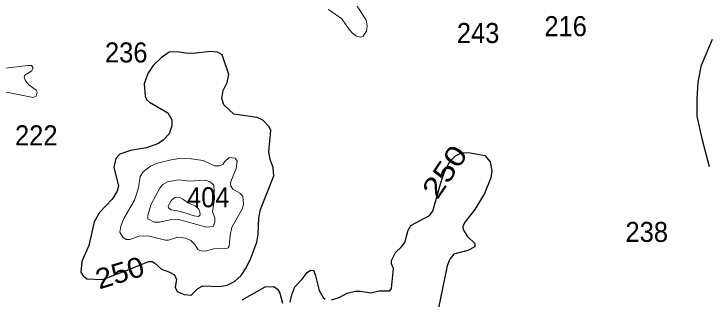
# Model space of a CAD drawing. Extents: x 499.9 to 555.3, y 9281.5 to 9336.8.
# Drawn here: x 526.97 to 532.51, y 9290.82 to 9293.1 of the extents above; entities that cross this region are included whole.
import ezdxf
from ezdxf.enums import TextEntityAlignment as Align

# ---------------------------------------------------------------- set-up
doc = ezdxf.new("R2010")
doc.units = 0
doc.header["$LTSCALE"] = 0.064
doc.layers.add('1', color=7, linetype='Continuous', lineweight=25)
doc.layers.add('2', color=7, linetype='Continuous', lineweight=13)
doc.layers.add('21', color=7, linetype='Continuous')
doc.layers.add('61', color=7, linetype='Continuous')

msp = doc.modelspace()

# ---------------------------------------------------------------- linework, layer by layer
at = {"layer": '1'}
for points in [[(532.5213, 9291.877), (532.4646, 9292.0881), (532.4233, 9292.2803), (532.4227, 9292.419), (532.4306, 9292.551), (532.4564, 9292.6863), (532.5451, 9292.8957)], [(530.0159, 9291.1934), (530.0639, 9291.2373), (530.092, 9291.2732), (530.1179, 9291.3716), (530.1405, 9291.4089), (530.288, 9291.4891), (530.3148, 9291.5231), (530.3747, 9291.7412), (530.4073, 9291.8356), (530.4498, 9291.9184), (530.4959, 9291.9634), (530.5497, 9291.9912), (530.6114, 9291.9884), (530.7298, 9291.9661), (530.7731, 9291.9174), (530.7848, 9291.8421), (530.777, 9291.7887), (530.728, 9291.6629), (530.6485, 9291.5355), (530.5686, 9291.4346), (530.5546, 9291.4018), (530.5579, 9291.3766), (530.5897, 9291.3234), (530.6502, 9291.2639), (530.6495, 9291.2397), (530.5947, 9291.21), (530.4827, 9291.1796), (530.4512, 9291.1391), (530.4291, 9291.0863), (530.3602, 9290.7522)], [(529.9719, 9290.8879), (529.9843, 9290.9053), (530.0016, 9291.0645), (529.9846, 9291.102), (529.986, 9291.1283), (530.0159, 9291.1934)], [(529.1775, 9290.7972), (529.1902, 9290.8552), (529.2147, 9290.9195), (529.2739, 9290.9804), (529.3128, 9291.0334), (529.3383, 9291.0523), (529.3662, 9291.0505), (529.3726, 9291.0302), (529.3785, 9291.0076), (529.4084, 9290.8903), (529.4396, 9290.8337), (529.4555, 9290.8203)], [(528.7957, 9290.8148), (528.9778, 9290.9185), (529.0479, 9290.9232), (529.077, 9290.8996), (529.0954, 9290.8678), (529.1156, 9290.7887)], [(529.5078, 9290.8166), (529.5673, 9290.8347), (529.6319, 9290.8697), (529.6947, 9290.8853), (529.7384, 9290.8854), (529.8212, 9290.8713), (529.8866, 9290.887), (529.9719, 9290.8879)]]:
    msp.add_lwpolyline(points, dxfattribs=at)
msp.add_lwpolyline([(527.6817, 9290.9779), (527.8441, 9291.0399), (528.0494, 9291.1223), (528.0769, 9291.1214), (528.0981, 9291.1086), (528.1507, 9291.0616), (528.2113, 9291.0394), (528.2556, 9291.0142), (528.2716, 9290.9787), (528.2597, 9290.9167), (528.2756, 9290.8825), (528.333, 9290.8583), (528.3887, 9290.8522), (528.44, 9290.907), (528.482, 9290.9282), (528.6166, 9290.9227), (528.6761, 9290.9318), (528.7342, 9290.9631), (528.7855, 9291.0098), (528.8225, 9291.0638), (528.8616, 9291.1403), (528.911, 9291.2766), (528.9235, 9291.3382), (528.9276, 9291.4688), (528.9405, 9291.5372), (529.0467, 9291.8039), (529.0421, 9291.8698), (529.017, 9291.9336), (529.0073, 9291.9972), (529.0227, 9292.1658), (529.0112, 9292.1959), (528.9602, 9292.2496), (528.9142, 9292.2693), (528.7279, 9292.2956), (528.6481, 9292.3699), (528.632, 9292.4202), (528.6441, 9292.4842), (528.6743, 9292.5488), (528.6885, 9292.6123), (528.6352, 9292.7684), (528.5981, 9292.7912), (528.536, 9292.7952), (528.4076, 9292.7811), (528.3418, 9292.7827), (528.2782, 9292.7936), (528.2122, 9292.7904), (528.1499, 9292.7465), (528.0847, 9292.6843), (528.0431, 9292.6216), (528.0142, 9292.5372), (528.0204, 9292.4412), (528.0327, 9292.4129), (528.0556, 9292.3916), (528.202, 9292.3076), (528.2332, 9292.2516), (528.2349, 9292.2042), (528.2138, 9292.1407), (528.1667, 9292.092), (528.1269, 9292.0634), (528.0307, 9292.0286), (527.9047, 9292.0063), (527.8199, 9291.9771), (527.7882, 9291.9422), (527.7724, 9291.873), (527.8084, 9291.7226), (527.7992, 9291.6836), (527.7576, 9291.6193), (527.6575, 9291.5125), (527.6134, 9291.4384), (527.572, 9291.2489), (527.5162, 9291.1202), (527.5085, 9291.036), (527.5283, 9291.0059), (527.5558, 9290.9829)], close=True, dxfattribs=at)
at = {"layer": '2'}
for points in [[(529.4832, 9293.1312), (529.5895, 9293.0562), (529.6465, 9292.9727), (529.6772, 9292.9387), (529.706, 9292.9182), (529.7377, 9292.9113), (529.7587, 9292.9187), (529.7864, 9292.959), (529.79, 9293.0007), (529.7836, 9293.0451), (529.7047, 9293.1719)], [(526.6326, 9292.5279), (527.1289, 9292.4298), (527.1529, 9292.4394), (527.1607, 9292.4722), (527.1528, 9292.488), (527.0949, 9292.5309), (527.0673, 9292.5615), (527.0565, 9292.5916), (527.0622, 9292.6083), (527.1185, 9292.6431), (527.1259, 9292.6581), (527.1258, 9292.6697), (527.1179, 9292.6827), (527.1139, 9292.6847), (527.086, 9292.6853), (526.9088, 9292.6642)]]:
    msp.add_lwpolyline(points, dxfattribs=at)
for points in [[(528.7967, 9291.5436), (528.804, 9291.5788), (528.8001, 9291.6413), (528.7754, 9291.6665), (528.7206, 9291.6993), (528.7025, 9291.727), (528.7044, 9291.7607), (528.7458, 9291.8637), (528.7536, 9291.9204), (528.7393, 9291.9467), (528.6909, 9291.9503), (528.6541, 9291.9172), (528.6406, 9291.8962), (528.6109, 9291.8835), (528.5742, 9291.8851), (528.4843, 9291.9264), (528.3881, 9291.9405), (528.2917, 9291.9423), (528.229, 9291.9334), (528.1207, 9291.9046), (528.0648, 9291.8824), (528.0052, 9291.8359), (527.9818, 9291.8006), (527.9691, 9291.7099), (527.9375, 9291.61), (527.8514, 9291.4653), (527.826, 9291.402), (527.8199, 9291.3547), (527.8433, 9291.3165), (527.8692, 9291.2977), (527.9001, 9291.2964), (527.9712, 9291.3227), (528.0433, 9291.3261), (528.1827, 9291.2914), (528.2086, 9291.2917), (528.2822, 9291.3152), (528.3465, 9291.3084), (528.3848, 9291.2896), (528.4152, 9291.2604), (528.4437, 9291.2155), (528.466, 9291.2055), (528.5017, 9291.2042), (528.5664, 9291.2231), (528.6696, 9291.2247), (528.6823, 9291.2295), (528.6919, 9291.2442), (528.6986, 9291.3312), (528.7118, 9291.3948)], [(528.577, 9291.4692), (528.5582, 9291.5173), (528.5745, 9291.6226), (528.5683, 9291.73), (528.5391, 9291.7558), (528.497, 9291.7688), (528.3737, 9291.7625), (528.2902, 9291.7735), (528.1989, 9291.7574), (528.1631, 9291.7348), (528.1394, 9291.706), (528.0685, 9291.5785), (528.0427, 9291.4912), (528.0437, 9291.4624), (528.0937, 9291.4348), (528.1357, 9291.4348), (528.2178, 9291.4537), (528.2784, 9291.46), (528.5092, 9291.3949), (528.5642, 9291.4016), (528.5755, 9291.436)], [(528.3021, 9291.5215), (528.4114, 9291.4846), (528.4475, 9291.4814), (528.4598, 9291.4934), (528.4571, 9291.5174), (528.4491, 9291.5388), (528.421, 9291.5656), (528.3676, 9291.587), (528.3222, 9291.6174), (528.2932, 9291.6343), (528.2591, 9291.6316), (528.2302, 9291.6105), (528.2056, 9291.5617), (528.2074, 9291.5503), (528.2281, 9291.5334)]]:
    msp.add_lwpolyline(points, close=True, dxfattribs=at)

# ---------------------------------------------------------------- texts
at = {"layer": '21', "width": 0.95}
for s, p in [('216', (531.2039, 9292.9184)), ('243', (530.5061, 9292.8636)), ('236', (527.7008, 9292.7088)), ('222', (526.9836, 9292.0476)), ('404', (528.3552, 9291.5539)), ('238', (531.8507, 9291.2776))]:
    msp.add_text(s, height=0.16, dxfattribs=at).set_placement(p)
at = {"layer": '61'}
for rotation, width, p in [(55.84, 1.25, (530.4752, 9291.7932)), (17.162, 1.1, (527.8423, 9290.9557))]:
    msp.add_text('250', height=0.16, rotation=rotation, dxfattribs=dict(at, width=width)).set_placement(p, align=Align.CENTER)

doc.saveas('drawing.dxf')
